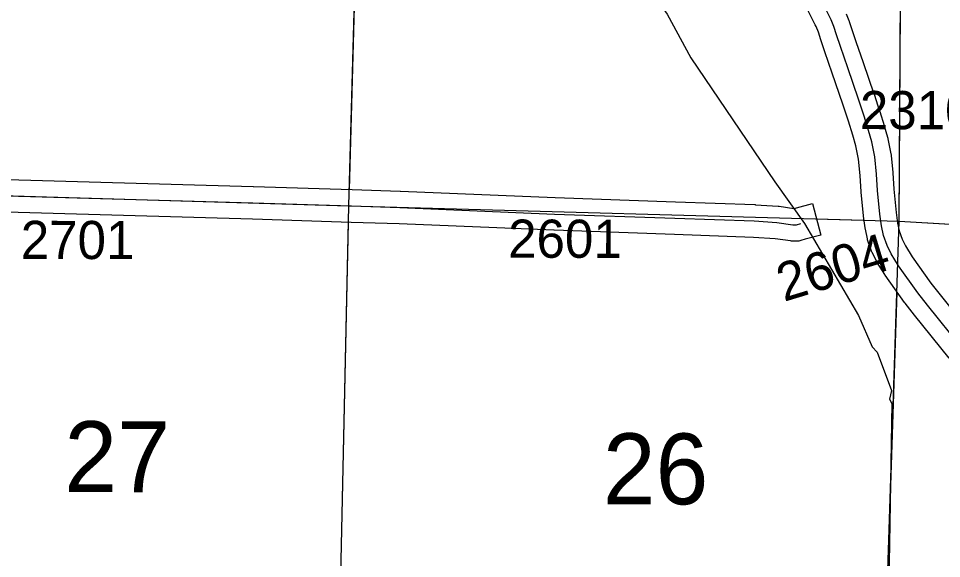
# Model space of a CAD drawing. Extents: x -157.2 to -99.3, y 12.2 to 46.2.
# Drawn here: x -137.475 to -135.784, y 24.227 to 25.218 of the extents above; entities that cross this region are included whole.
import ezdxf

# ---------------------------------------------------------------- set-up
doc = ezdxf.new("R2010")
doc.units = 0
for name, color, linetype in [('tdCoHydroRiver', 7, 'Continuous'), ('tdCoSecRdNmbr', 7, 'Continuous'), ('tdCoSecRteBand', 7, 'Continuous'), ('tdCoSecRteCL', 7, 'Continuous'), ('tdCoSectLine', 7, 'Continuous'), ('tdCoSectLinePart', 7, 'Continuous'), ('tdCoSectNmbr', 7, 'Continuous'), ('tdCoSurfAsphalt', 7, 'Continuous'), ('tdCoSurfGravel', 7, 'Continuous')]:
    doc.layers.add(name, color=color, linetype=linetype)

msp = doc.modelspace()

# ---------------------------------------------------------------- linework, layer by layer
at = {"layer": 'tdCoHydroRiver'}
msp.add_lwpolyline([(-136.9996, 25.8866), (-136.9856, 25.8815), (-136.4128, 25.4211), (-136.3672, 25.3659), (-136.3181, 25.2712), (-136.2863, 25.226), (-136.2431, 25.1456), (-136.0892, 24.9181), (-136.0347, 24.8421), (-135.9358, 24.6731), (-135.9108, 24.6155), (-135.9017, 24.6057), (-135.8754, 24.5354), (-135.8791, 24.5197), (-135.8746, 24.5117), (-135.8839, 23.9623), (-135.8603, 23.9095), (-135.8207, 23.8656), (-135.8193, 23.8576)], dxfattribs=at)
at = {"layer": 'tdCoSecRteBand'}
for points in [[(-135.7697, 24.5949), (-135.8329, 24.6735), (-135.833, 24.6736), (-135.833, 24.6737), (-135.8505, 24.6959), (-135.851, 24.6965), (-135.8515, 24.6972), (-135.8867, 24.747), (-135.8872, 24.7476), (-135.8876, 24.7483), (-135.9015, 24.7703), (-135.9023, 24.7716), (-135.903, 24.773), (-135.9104, 24.7881), (-135.9112, 24.7896), (-135.9117, 24.7913), (-135.9184, 24.81), (-135.9191, 24.8119), (-135.9195, 24.8138), (-135.9232, 24.8314), (-135.9234, 24.8326), (-135.9236, 24.8338), (-135.9263, 24.8552), (-135.9264, 24.8557), (-135.9264, 24.8561), (-135.9306, 24.8993), (-135.9306, 24.8996), (-135.9306, 24.9), (-135.9328, 24.93), (-135.9356, 24.9597), (-135.9405, 24.9842), (-135.9464, 25.0039), (-135.9543, 25.0296), (-135.9642, 25.0607), (-135.9838, 25.1178), (-135.9972, 25.1565), (-135.9972, 25.1566), (-135.9972, 25.1567), (-136.0046, 25.1786), (-136.0046, 25.1787), (-136.0046, 25.1787), (-136.0093, 25.1927), (-136.0135, 25.2033), (-136.015, 25.2063), (-136.0154, 25.2061), (-136.0282, 25.2319)], [(-135.9582, 25.2265), (-135.9533, 25.2142), (-135.9529, 25.2133), (-135.9527, 25.2125), (-135.9477, 25.1978), (-135.9404, 25.176), (-135.9271, 25.1373), (-135.9271, 25.1373), (-135.9271, 25.1373), (-135.9074, 25.0798), (-135.9073, 25.0796), (-135.9072, 25.0793), (-135.8971, 25.0477), (-135.897, 25.0475), (-135.8969, 25.0473), (-135.889, 25.0214), (-135.889, 25.0214), (-135.889, 25.0213), (-135.8826, 25.0001), (-135.8822, 24.9987), (-135.8819, 24.9973), (-135.8765, 24.9699), (-135.8762, 24.9684), (-135.876, 24.9669), (-135.8731, 24.9353), (-135.873, 24.935), (-135.873, 24.9347), (-135.8708, 24.9047), (-135.8667, 24.8623), (-135.8642, 24.8425), (-135.8612, 24.8282), (-135.8558, 24.813), (-135.8498, 24.8009), (-135.8373, 24.781), (-135.803, 24.7325), (-135.786, 24.711), (-135.723, 24.6324)], [(-137.5394, 24.9239), (-137.0449, 24.9098), (-137.0449, 24.9098), (-137.0448, 24.9098), (-136.8637, 24.904), (-136.7755, 24.9012), (-136.7754, 24.9012), (-136.7753, 24.9011), (-136.4915, 24.8893), (-136.2711, 24.8814), (-136.1257, 24.8765), (-136.1251, 24.8765), (-136.1246, 24.8764), (-136.0831, 24.8736), (-136.0821, 24.8735), (-136.0812, 24.8734), (-136.0543, 24.8697), (-136.0531, 24.8697), (-136.0492, 24.8708), (-136.0202, 24.8786), (-136.0045, 24.8207), (-136.0335, 24.8129), (-136.0413, 24.8108), (-136.0451, 24.8097), (-136.0491, 24.8097), (-136.0563, 24.8097), (-136.0583, 24.8097), (-136.0603, 24.81), (-136.0882, 24.8138), (-136.1282, 24.8165), (-136.2732, 24.8215), (-136.2732, 24.8215), (-136.2733, 24.8215), (-136.4937, 24.8294), (-136.4938, 24.8294), (-136.4939, 24.8294), (-136.7776, 24.8412), (-136.8656, 24.844), (-137.0467, 24.8498), (-137.5411, 24.8639)]]:
    msp.add_lwpolyline(points, dxfattribs=at)
at = {"layer": 'tdCoSecRteCL'}
for points in [[(-135.7464, 24.6136), (-135.8095, 24.6923), (-135.827, 24.7145), (-135.8623, 24.7643), (-135.8761, 24.7863), (-135.8835, 24.8013), (-135.8901, 24.82), (-135.8938, 24.8376), (-135.8965, 24.859), (-135.9007, 24.9022), (-135.9029, 24.9325), (-135.9059, 24.9641), (-135.9113, 24.9914), (-135.9177, 25.0126), (-135.9256, 25.0385), (-135.9357, 25.0701), (-135.9555, 25.1276), (-135.9688, 25.1663), (-135.9762, 25.1882), (-135.9811, 25.203), (-135.9861, 25.2154), (-135.9915, 25.2267), (-135.9981, 25.24), (-136.0019, 25.2463)], [(-137.5402, 24.8939), (-137.0458, 24.8798), (-136.8647, 24.874), (-136.7765, 24.8712), (-136.4927, 24.8593), (-136.2722, 24.8514), (-136.1267, 24.8465), (-136.0852, 24.8436), (-136.0563, 24.8397), (-136.0491, 24.8397), (-136.0413, 24.8418)]]:
    msp.add_lwpolyline(points, dxfattribs=at)
at = {"layer": 'tdCoSectLine'}
for points in [[(-136.8696, 24.8741), (-136.8424, 25.8744)], [(-135.861, 24.8463), (-135.8551, 25.8253)], [(-137.8551, 24.9036), (-136.8696, 24.8741)], [(-136.8911, 23.8845), (-136.8696, 24.8741)], [(-136.8696, 24.8741), (-135.861, 24.8463)], [(-135.8934, 23.8472), (-135.861, 24.8463)], [(-135.861, 24.8463), (-134.8895, 24.789)]]:
    msp.add_lwpolyline(points, dxfattribs=at)
at = {"layer": 'tdCoSectLinePart'}
for points in [[(-136.8688, 24.9039), (-136.8432, 25.8442)], [(-135.861, 24.8463), (-135.8585, 25.2635)], [(-136.8905, 23.9145), (-136.8703, 24.8439)], [(-136.013, 24.8505), (-135.9258, 24.8481)], [(-135.8645, 24.8464), (-135.861, 24.8463)], [(-135.8616, 24.8284), (-135.861, 24.8463)], [(-135.861, 24.8463), (-134.9072, 24.79)], [(-135.8925, 23.8772), (-135.8652, 24.7161)]]:
    msp.add_lwpolyline(points, dxfattribs=at)
at = {"layer": 'tdCoSurfAsphalt'}
msp.add_lwpolyline([(-135.7464, 24.6136), (-135.8095, 24.6923), (-135.827, 24.7145), (-135.8623, 24.7643), (-135.8761, 24.7863), (-135.8835, 24.8013), (-135.8901, 24.82), (-135.8938, 24.8376), (-135.8965, 24.859), (-135.9007, 24.9022), (-135.9029, 24.9325), (-135.9059, 24.9641), (-135.9113, 24.9914), (-135.9177, 25.0126), (-135.9256, 25.0385), (-135.9357, 25.0701), (-135.9555, 25.1276), (-135.9688, 25.1663), (-135.9762, 25.1882), (-135.9811, 25.203), (-135.9861, 25.2154), (-135.9915, 25.2267)], dxfattribs=at)
at = {"layer": 'tdCoSurfGravel'}
msp.add_lwpolyline([(-137.5402, 24.8939), (-137.0458, 24.8798), (-136.8647, 24.874), (-136.7765, 24.8712), (-136.4927, 24.8593), (-136.2722, 24.8514), (-136.1267, 24.8465), (-136.0852, 24.8436), (-136.0563, 24.8397), (-136.0491, 24.8397), (-136.0413, 24.8418)], dxfattribs=at)

# ---------------------------------------------------------------- texts
at = {"layer": 'tdCoSecRdNmbr'}
for s, rotation, p in [('2310', 359.8967, (-135.9333, 25.015)), ('2701', 359.8957, (-137.4712, 24.7769)), ('2601', 359.8964, (-136.578, 24.7791)), ('2604', 16.9282, (-136.0727, 24.6979))]:
    msp.add_text(s, height=0.07, rotation=rotation, dxfattribs=at).set_placement(p)
at = {"layer": 'tdCoSectNmbr'}
for s, rotation, p in [('27', 359.8957, (-137.3913, 24.3492)), ('26', 359.8965, (-136.4044, 24.327))]:
    msp.add_text(s, height=0.13, rotation=rotation, dxfattribs=at).set_placement(p)

doc.saveas('drawing.dxf')
